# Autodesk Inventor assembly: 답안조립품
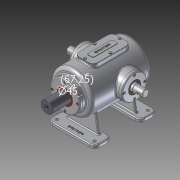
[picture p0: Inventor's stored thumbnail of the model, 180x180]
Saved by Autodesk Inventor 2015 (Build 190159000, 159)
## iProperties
Created: 2016-02
Part Number: 답안조립품
Document SubType Name: Assembly
Designer: Administrator
Mass: 8191.33 g
Surface Area: 4241.86 cm^2
Volume: 1855.51 cm^3
Density: 4.41461 g/cm^3
Author: Administrator
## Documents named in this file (15)
- C:\Users\Administrator\Desktop\360220V1009\답안조립품.iam
- C:\Users\Administrator\Desktop\360220V1009\본체.ipt
- C:\Users\Administrator\Desktop\360220V1009\상부커버.ipt
- C:\Users\Administrator\Desktop\360220V1009\축 커버.ipt
- C:\Users\Administrator\Desktop\360220V1009\육각머리볼트 M4.ipt
- C:\Users\Administrator\Desktop\360220V1009\오일실.ipt
- 오일실.ipt
- C:\Users\Administrator\Desktop\360220V1009\볼트 M4x0.7.ipt
- C:\Users\Administrator\Desktop\360220V1009\슬라이드 커버.ipt
- C:\Users\Administrator\Desktop\360220V1009\부시.ipt
- C:\Users\Administrator\Desktop\360220V1009\베어링 6205.ipt
- 베어링 6205.ipt
- C:\Users\Administrator\Desktop\360220V1009\편심축.ipt
- C:\Users\Administrator\Desktop\360220V1009\가변스프링.ipt
- C:\Users\Administrator\Desktop\360220V1009\슬라이드.ipt
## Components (13 placed, 2 different names)
1. 가변스프링:1
2. M4x0.7:1
3. M4x0.7:3
4. M4x0.7:4
5. M4x0.7:5
6. M4x0.7:2
7. M4x0.7:6
8. M4x0.7:7
9. M4x0.7:8
10. M4x0.7:9
11. M4x0.7:10
12. M4x0.7:11
13. M4x0.7:12
